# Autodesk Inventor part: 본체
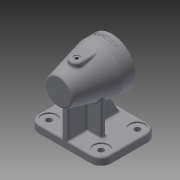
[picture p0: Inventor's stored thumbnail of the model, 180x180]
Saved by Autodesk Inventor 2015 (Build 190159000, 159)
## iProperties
Created: 2024-12
Part Number: 본체
Material: 일반
Document SubType Name: Modeling
Designer: 10401
Density: 1 g/cm^3
Appearance: 기본값
Author: 10401
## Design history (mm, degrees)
sketch "스케치1"
  geometry: L1 (-57, 44.5)-(57, 44.5); L2 (57, 44.5)-(57, -44.5); L3 (57, -44.5)-(-57, -44.5); L4 (-57, -44.5)-(-57, 44.5); L5 (-57, 44.5)-(57, -44.5); L6 (57, 44.5)-(-57, -44.5); 1 further point
  constraints: 12 end point, 2 midpoint, 2 parallel, 1 horizontal, 1 perpendicular
  dimensions: "d0" = 114 distance of L1.start L1.end; "d1" = 89 distance of L1.end L2.end
extrude "돌출1" new body sketch "스케치1" distance "d2" = 12; taper "d3" = 0 deg
fillet "모깎기1" dims "d4" = 16
sketch "스케치2"
  geometry: A1 r 16 centre (-41, 28.5) between (-41, 44.5) and (-57, 28.5) reference; A2 r 16 centre (-41, -28.5) between (-57, -28.5) and (-41, -44.5) reference; A3 r 16 centre (41, -28.5) between (41, -44.5) and (57, -28.5) reference; A4 r 16 centre (41, 28.5) between (57, 28.5) and (41, 44.5) reference; 1 further point
hole "구멍1" sketch "스케치2" at (41, 28.5), (41, -28.5), (-41, -28.5), (-41, 28.5) diameter "d5" = 9; stored, may be unused: countersink angle "d9" = 90 deg, drill point angle "d11" = 118 deg; dims "d6" = 6, "d7" = 24, "d8" = 2, "d10" = 8
sketch "스케치3"
  geometry: L1 (-41, -44.5)-(41, -44.5) reference; L2 (41, 44.5)-(-41, 44.5) reference; L3 (-5, 44.5)-(5, 44.5); L4 (5, 44.5)-(5, -37.5); L5 (5, -37.5)-(-5, -37.5); L6 (-5, -37.5)-(-5, 44.5); L7 (0, 0)-(0, 13.919)
  constraints: 10 end point, 2 parallel, 1 horizontal, 1 perpendicular, 1 point on line, 1 vertical, 1 other
  dimensions: "d13" = 10 distance of L4.end L5.end; "d14" = 7 distance between parallel lines of L1 L5
extrude "돌출2" join sketch "스케치3" distance "d15" = 70; taper "d16" = 0 deg
sketch "스케치4"
  geometry: L1 (-5, 44.5)-(-41, 44.5) reference; L2 (-28, 15.5)-(28, 15.5); L3 (28, 15.5)-(28, 7.5); L4 (28, 7.5)-(-28, 7.5); L5 (-28, 7.5)-(-28, 15.5); L6 (0, 0)-(0, 11.5)
  constraints: 10 end point, 2 parallel, 1 horizontal, 1 perpendicular, 1 vertical, 1 other
  dimensions: "d17" = 56 distance of L2.start L2.end; "d18" = 8 distance of L2.end L3.end; "d19" = 29 distance between parallel lines of L2 L1
extrude "돌출3" join sketch "스케치4" distance "d20" = 70; taper "d21" = 0 deg
feature "면 기울기1" dims angle "d22" = 30 deg
sketch "스케치5"
  geometry: L1 (54.5, 82)-(54.5, 103); L2 (-9.5, 119)-(-29.5, 119); L3 (-29.5, 119)-(-29.5, 82); L4 (-29.5, 82)-(54.5, 82); L5 (28.5, 0)-(-28.5, 0) reference; L6 (-44.5, 12)-(-44.5, 0) reference; L7 (54.5, 103)-(-9.5, 119); 1 further point
  constraints: 10 end point, 2 perpendicular, 1 vertical
  dimensions: "d23" = 20 distance of L2.start L2.end; "d24" = 119 distance between parallel lines of L5 L2; "d25" = 82 distance between parallel lines of L5 L4; "d28" = 21 distance of L1.start L1.end; "d29" = 15 distance between parallel lines of L6 L3; "d30" = 99 distance between parallel lines of L1 L6
revolve "회전1" sketch "스케치5" stored, may be unused: angle "d32" = 90 deg
sketch "스케치7"
  geometry: C1 r 37 at (0, 0) reference; C2 r 23.5 at (0, 0); 1 further point
  constraints: 1 centre point, 1 coincident
  dimensions: "d36" = 47 diameter of C2
extrude "돌출5" cut sketch "스케치7" distance "d37" = 18; taper "d38" = 0 deg
sketch "스케치8"
  geometry: L1 (54.5, 61)-(44.5, 58.5) reference; L2 (44.5, 58.5)-(44.5, 0) reference; L3 (44.5, 0)-(-44.5, 0) reference; L4 (-44.5, 0)-(-44.5, 12) reference; L5 (-44.5, 12)-(-37.5, 12) reference; L6 (-37.5, 12)-(-18.447, 45) reference; L7 (-18.447, 45)-(-29.5, 45) reference; L8 (-29.5, 45)-(-29.5, 58.5) reference; L9 (-29.5, 58.5)-(-11.5, 58.5) reference; L10 (-11.5, 58.5)-(-11.5, 105.5) reference; L11 (-11.5, 105.5)-(-29.5, 105.5) reference; L12 (-29.5, 105.5)-(-29.5, 119) reference; L13 (-29.5, 119)-(-9.5, 119) reference; L14 (-9.5, 119)-(54.5, 103) reference; L15 (54.5, 103)-(54.5, 61) reference; L16 (33.5, 103.096)-(-11.5, 114.346); L17 (-11.5, 114.346)-(-11.5, 105.5); L18 (-11.5, 82)-(33.5, 82); L19 (33.5, 82)-(33.5, 103.096); 1 further point
  constraints: 8 end point, 1 horizontal, 1 midpoint, 1 parallel, 1 perpendicular, 1 vertical
  dimensions: "d39" = 5 distance between parallel lines of L16 L14; "d40" = 45 horizontal distance of L16.end L16.start
revolve "회전2" sketch "스케치8" stored, may be unused: angle "d41" = 90 deg
sketch "스케치9"
  geometry: C1 r 21.096 at (0, 0) reference; C2 r 17.5 at (0, 0); 1 further point
  constraints: 1 centre point, 1 coincident
  dimensions: "d42" = 35 diameter of C2
extrude "돌출6" cut sketch "스케치9" distance "d43" = 10; taper "d44" = 0 deg
sketch "스케치10"
  geometry: C1 r 17.5 at (0, 0) reference; C2 r 15.5 at (0, 0); 1 further point
  constraints: 1 centre point, 1 coincident
  dimensions: "d45" = 31 diameter of C2
extrude "돌출7" cut sketch "스케치10" distance "d46" = 3; taper "d47" = 0 deg
fillet "모깎기3" dims "d48" = 3
fillet "모깎기4" dims "d49" = 0.3
fillet "모깎기5" dims "d50" = 3
chamfer "모따기1" distance "d51" = 1; stored, may be unused: second distance "d52" = 2, angle "d53" = 45 deg
fillet "모깎기6" dims "d54" = 5
chamfer "모따기2" distance "d55" = 1; stored, may be unused: second distance "d56" = 2, angle "d57" = 45 deg
fillet "모깎기7" dims "d58" = 3
fillet "모깎기9" dims "d68" = 3
fillet "모깎기10" dims "d69" = 3
fillet "모깎기11" dims "d70" = 3
sketch "스케치16"
  geometry: C1 r 37 at (0, 0) reference; 2 further points
  constraints: 1 vertical alignment
  dimensions: "d78" = 28.5 distance of C1.centre point (0, 28.5)
hole "구멍2" sketch "스케치16" at (0, 28.5) diameter "d79" = 3.242; stored, may be unused: countersink angle "d83" = 90 deg, drill point angle "d85" = 118 deg; dims "d80" = 8, "d81" = 4, "d82" = 2, "d84" = 10
node "작업 평면2"
sketch "스케치18"
  geometry: L1 (16.733, -9.869)-(16.733, -29.5) reference; L2 (16.733, -29.5)-(-16.733, -29.5) reference; L3 (-16.733, -29.5)-(-16.733, -9.869) reference; L4 (10.63, 26.5)-(10.63, -0.179); L5 (-9.37, 26.5)-(-9.37, 1.282); L6 (0.63, 6.476)-(0.63, -6.949); A1 r 10 centre (0.63, 26.5) between (10.63, 26.5) and (-9.37, 26.5); 3 further points
  constraints: 6 end point, 2 horizontal alignment, 2 perpendicular, 2 point on circle, 1 centre point, 1 vertical, 7 other
  dimensions: "d92" = 20 diameter of A1; "d107" = 56 distance from line of L2 A1.centre
extrude "돌출10" join sketch "스케치18" stored distance "d93" = 20; taper "d94" = 0 deg
fillet "모깎기12" dims "d95" = 3
sketch "스케치19"
  geometry: A1 r 7 centre (-0.63, 26.5) between (6.37, 26.5) and (-7.63, 26.5) reference; 1 further point
hole "구멍3" sketch "스케치19" at (-0.63, 26.5) diameter "d96" = 5.188; stored, may be unused: countersink angle "d100" = 90 deg, drill point angle "d102" = 118 deg; dims "d97" = 12, "d98" = 10, "d99" = 1, "d101" = 20
node "작업 평면3"
sketch "스케치20"
  geometry: L1 (37, -29.5)-(-37, -29.5) reference; 2 further points
  constraints: 1 vertical alignment, 1 other
  dimensions: "d104" = 9 distance from line of L1 point (0, -20.5)
feature "엠보싱2" sketch "스케치20" dims "d0" = 114, "d1" = 89, "d105" = 0.5, "d106" = 0
node "솔리드1"
pattern_circular "원형 패턴1" dims angle "d87" = 360 deg
node "절단 모서리 투영1"
node "절단 모서리 투영3"
other parameters: "d91" = -115, "d103" = -119
